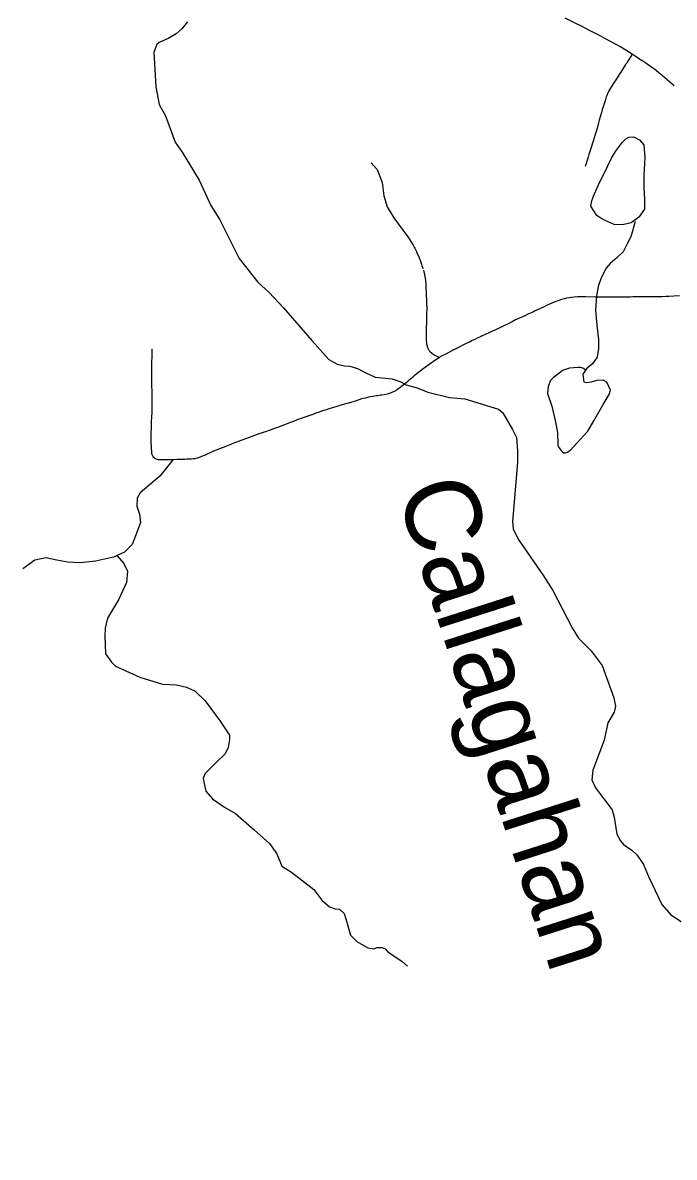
# Model space of a CAD drawing. Extents: x -19 to 366, y -4 to 359.
# Drawn here: x 143.365 to 144.057, y 187.329 to 188.535 of the extents above; entities that cross this region are included whole.
import ezdxf

# ---------------------------------------------------------------- set-up
doc = ezdxf.new("R2010")
doc.units = 0
for name, color, linetype in [('R_ROW', 7, 'Continuous'), ('R_ROW Annot', 7, 'Continuous'), ('R_Temp Easement', 7, 'Continuous'), ('Sheet Fence', 7, 'Continuous'), ('T_Indications', 7, 'Continuous')]:
    doc.layers.add(name, color=color, linetype=linetype)

msp = doc.modelspace()

# ---------------------------------------------------------------- linework, layer by layer
at = {"layer": 'R_ROW'}
for points in [[(144.0128, 188.5014), (144.0042, 188.5069), (143.9996, 188.5096), (143.9959, 188.5118), (143.9906, 188.5146), (143.9838, 188.5183), (143.9788, 188.5209), (143.9708, 188.5251), (143.9681, 188.5265), (143.9576, 188.5319), (143.9551, 188.5332), (143.9417, 188.54)], [(144.0128, 188.5014), (144.0075, 188.4931), (144.0069, 188.4921), (144.0062, 188.4912), (144.0057, 188.4904), (144.0036, 188.4871), (144.0006, 188.4823), (143.9997, 188.481), (143.9977, 188.478), (143.9967, 188.4764), (143.9931, 188.471), (143.9926, 188.4701), (143.9908, 188.4672), (143.9897, 188.4655), (143.9877, 188.4619), (143.987, 188.4606), (143.9858, 188.4576), (143.9854, 188.4567), (143.9852, 188.4561), (143.9839, 188.452), (143.9829, 188.4487), (143.9822, 188.4466), (143.9809, 188.4427), (143.98, 188.4397), (143.9786, 188.4348), (143.9778, 188.4314), (143.977, 188.4286), (143.9762, 188.4253), (143.9749, 188.4205), (143.9735, 188.4161), (143.9714, 188.4091), (143.9707, 188.4071), (143.9691, 188.4025), (143.9681, 188.3993), (143.9667, 188.3949), (143.9659, 188.3922), (143.9627, 188.3822)], [(144.0575, 188.4679), (144.045, 188.4785), (144.0431, 188.48), (144.0363, 188.4855), (144.0346, 188.4868), (144.0288, 188.4909), (144.0273, 188.492), (144.0231, 188.4948), (144.0217, 188.4957), (144.0207, 188.4964), (144.0192, 188.4974), (144.0128, 188.5014)], [(143.7909, 188.2721), (143.7914, 188.2702), (143.7916, 188.2691), (143.792, 188.2671), (143.7928, 188.2633), (143.7929, 188.2626), (143.7931, 188.2612), (143.7933, 188.2597), (143.7934, 188.2587), (143.7934, 188.2578), (143.7937, 188.2544), (143.7937, 188.2537), (143.794, 188.247), (143.794, 188.246), (143.7943, 188.2393), (143.7943, 188.2381), (143.7944, 188.2345), (143.7945, 188.234), (143.7945, 188.2314), (143.7945, 188.2304), (143.7944, 188.2256), (143.7943, 188.2226), (143.7941, 188.214), (143.794, 188.2123), (143.794, 188.2088), (143.794, 188.2041), (143.794, 188.1998), (143.794, 188.1976), (143.794, 188.1967), (143.7941, 188.1953), (143.7943, 188.1944), (143.7944, 188.1936), (143.7947, 188.1924), (143.7949, 188.1915), (143.795, 188.1909), (143.7954, 188.1898), (143.7956, 188.1894), (143.7962, 188.1881), (143.7965, 188.1876), (143.7968, 188.1871), (143.7976, 188.1859), (143.7986, 188.1848), (143.7991, 188.1843), (143.7999, 188.1834), (143.8007, 188.1829), (143.8014, 188.1825), (143.8019, 188.1822), (143.8028, 188.1817), (143.8038, 188.1812), (143.8079, 188.1792)], [(144.0632, 188.2447), (144.057, 188.2443), (144.0517, 188.2441), (144.0484, 188.244), (144.0446, 188.2437), (144.0422, 188.2436), (144.032, 188.2436), (144.0277, 188.2436), (144.0133, 188.2435), (144.0109, 188.2434), (144.0025, 188.2433), (143.9996, 188.2433), (143.9963, 188.2433), (143.9871, 188.2433), (143.9785, 188.2434), (143.9736, 188.2434), (143.9635, 188.2435), (143.9612, 188.2436), (143.9578, 188.2435), (143.9545, 188.2435), (143.951, 188.2433), (143.9482, 188.243), (143.9462, 188.2427), (143.9429, 188.2421), (143.9407, 188.2416), (143.9377, 188.2407), (143.934, 188.2395), (143.9315, 188.2386), (143.9274, 188.2369), (143.925, 188.2358), (143.9219, 188.2343), (143.9192, 188.233), (143.909, 188.2282), (143.9073, 188.2274), (143.902, 188.225), (143.8995, 188.2238), (143.8954, 188.222), (143.8889, 188.219), (143.8852, 188.2171), (143.8823, 188.2157), (143.8764, 188.2128), (143.8714, 188.2104), (143.8645, 188.2072), (143.8566, 188.2036), (143.8535, 188.2022), (143.8515, 188.2012), (143.8481, 188.1995), (143.8456, 188.1983), (143.8429, 188.197), (143.8398, 188.1955), (143.8371, 188.1942), (143.8261, 188.1888), (143.8232, 188.1873), (143.8223, 188.1868), (143.8212, 188.1862), (143.8166, 188.1838), (143.8161, 188.1835), (143.8154, 188.1831), (143.8141, 188.1824), (143.8122, 188.1816), (143.8097, 188.1804), (143.8093, 188.1802), (143.8084, 188.1795), (143.8079, 188.1792)], [(143.5025, 188.1883), (143.5023, 188.1813), (143.5022, 188.1728), (143.5021, 188.1698), (143.5022, 188.1628), (143.5022, 188.1603), (143.5022, 188.1567), (143.5022, 188.1542), (143.5022, 188.1517), (143.5022, 188.1485), (143.5024, 188.1435), (143.5025, 188.1392), (143.5025, 188.1362), (143.5025, 188.1326), (143.5023, 188.1281), (143.5023, 188.1258), (143.5023, 188.1211), (143.5023, 188.1199), (143.5021, 188.1166), (143.502, 188.1143), (143.5019, 188.1123), (143.5018, 188.1068), (143.5017, 188.1038), (143.5015, 188.0983), (143.5015, 188.0975), (143.5014, 188.0925), (143.5014, 188.089), (143.5015, 188.0874), (143.5017, 188.0855), (143.5019, 188.0825), (143.5019, 188.0815), (143.502, 188.0798), (143.502, 188.0786), (143.5022, 188.0774), (143.5024, 188.0765), (143.5026, 188.0759), (143.5033, 188.0747), (143.5035, 188.0744), (143.5037, 188.074), (143.5045, 188.0731), (143.5049, 188.0727), (143.5058, 188.072), (143.5063, 188.0718), (143.5067, 188.0715), (143.5076, 188.0711), (143.5082, 188.0709), (143.5091, 188.0708), (143.5136, 188.0707), (143.5171, 188.0706), (143.5179, 188.0706), (143.5223, 188.0707), (143.5238, 188.0707), (143.5293, 188.0709), (143.5327, 188.071), (143.5375, 188.0711), (143.5395, 188.0712), (143.5432, 188.0713), (143.5445, 188.0714), (143.5469, 188.0716), (143.5477, 188.0717), (143.5484, 188.0718), (143.5489, 188.0719)], [(143.8079, 188.1792), (143.8055, 188.1774), (143.8039, 188.1764), (143.8021, 188.1751), (143.8003, 188.1739), (143.7984, 188.1726), (143.7971, 188.1717), (143.7894, 188.166), (143.787, 188.1642), (143.7812, 188.1595), (143.7797, 188.1582), (143.7772, 188.1562), (143.776, 188.1552), (143.774, 188.1535), (143.7726, 188.1523), (143.7708, 188.1509), (143.7677, 188.1484), (143.7658, 188.1469), (143.7647, 188.146), (143.7635, 188.1452), (143.7621, 188.1442), (143.7615, 188.1438), (143.76, 188.143), (143.7575, 188.1418), (143.7566, 188.1415), (143.7524, 188.1401), (143.7494, 188.1395), (143.7467, 188.1391), (143.7455, 188.1389), (143.7427, 188.1384), (143.7412, 188.1382), (143.7371, 188.1375), (143.7352, 188.1372), (143.7328, 188.1368), (143.7314, 188.1365), (143.729, 188.136), (143.727, 188.1355), (143.7252, 188.135), (143.7207, 188.1335), (143.7195, 188.1332), (143.7149, 188.1317), (143.7113, 188.1307), (143.7097, 188.1303), (143.7048, 188.1288), (143.7011, 188.1277), (143.6999, 188.1273), (143.6945, 188.1257), (143.6904, 188.1244), (143.6869, 188.1232), (143.6849, 188.1226), (143.6793, 188.1207), (143.6778, 188.1201), (143.675, 188.1191), (143.6735, 188.1186), (143.6704, 188.1175), (143.6682, 188.1167), (143.6628, 188.1149), (143.6613, 188.1144), (143.6589, 188.1136), (143.6576, 188.1131), (143.6554, 188.1123), (143.6469, 188.1089), (143.6451, 188.1082), (143.6434, 188.1075), (143.6422, 188.107), (143.6362, 188.1048), (143.6345, 188.1042), (143.628, 188.1019), (143.6262, 188.1013), (143.6242, 188.1006), (143.6163, 188.0978), (143.6143, 188.0971), (143.6116, 188.0961), (143.6041, 188.0932), (143.6021, 188.0925), (143.5896, 188.0879), (143.5885, 188.0875), (143.5865, 188.0867), (143.5824, 188.0851), (143.5794, 188.0839), (143.5762, 188.0826), (143.5735, 188.0816), (143.568, 188.0794), (143.5671, 188.079), (143.5605, 188.0761), (143.559, 188.0754), (143.5551, 188.0737), (143.5538, 188.0732), (143.5516, 188.0724), (143.5506, 188.0722), (143.5489, 188.0719)]]:
    msp.add_lwpolyline(points, dxfattribs=at)
at = {"layer": 'R_ROW Annot'}
for points in [[(143.7354, 188.3861), (143.7418, 188.3791), (143.7471, 188.365), (143.7489, 188.3509), (143.7524, 188.3391), (143.7595, 188.3274), (143.7745, 188.3074), (143.7764, 188.3043), (143.7794, 188.2995), (143.78, 188.2984), (143.7812, 188.2963), (143.7819, 188.2952), (143.7828, 188.2932), (143.7835, 188.2917), (143.7845, 188.2897), (143.7856, 188.2871), (143.7864, 188.2852), (143.7871, 188.2835), (143.7889, 188.2783), (143.7894, 188.2767), (143.7901, 188.2747), (143.7905, 188.2733)], [(143.525, 188.0708), (143.511, 188.0528), (143.4899, 188.0353), (143.487, 188.0294), (143.4864, 188.0212), (143.4893, 188.0124), (143.4905, 188.0036), (143.487, 187.9943), (143.4817, 187.9802), (143.4735, 187.972), (143.4618, 187.9668), (143.4425, 187.9627), (143.4267, 187.9609), (143.4133, 187.9615), (143.4016, 187.9638), (143.3899, 187.9662), (143.3782, 187.9638), (143.3653, 187.9545)]]:
    msp.add_lwpolyline(points, dxfattribs=at)
at = {"layer": 'R_Temp Easement'}
for points in [[(143.5403, 188.5359), (143.5344, 188.5286), (143.5282, 188.5233), (143.5206, 188.5185), (143.5104, 188.5141), (143.5079, 188.512), (143.5045, 188.5036), (143.5068, 188.467), (143.5101, 188.448), (143.517, 188.4361), (143.5273, 188.408), (143.5348, 188.3972), (143.5527, 188.3675), (143.565, 188.3406), (143.5742, 188.3262), (143.5954, 188.2843), (143.6151, 188.2592), (143.6272, 188.2482), (143.6423, 188.2318), (143.6726, 188.1973), (143.6905, 188.1771), (143.6993, 188.172), (143.7073, 188.1701), (143.7128, 188.17), (143.7209, 188.1675), (143.7297, 188.1628), (143.7398, 188.1581), (143.7578, 188.1563), (143.7671, 188.1531), (143.7728, 188.1501), (143.7844, 188.1469), (143.7958, 188.1422), (143.8186, 188.1366), (143.8349, 188.1352), (143.8706, 188.1241)], [(144.0263, 188.3917), (144.025, 188.3725), (144.0253, 188.3589), (144.026, 188.3478), (144.026, 188.3368), (144.0197, 188.3282), (144.0118, 188.3222), (144.0026, 188.3203), (143.9937, 188.3206), (143.9839, 188.3247), (143.9795, 188.3273), (143.9751, 188.3301), (143.969, 188.3399), (143.97, 188.3456), (143.9716, 188.3506), (143.9766, 188.362), (143.9864, 188.3822), (143.9908, 188.3911), (143.9949, 188.398), (144.0025, 188.4081), (144.006, 188.4116), (144.0091, 188.4132), (144.0142, 188.4135), (144.0205, 188.4104), (144.0253, 188.4053), (144.0263, 188.3917)], [(144.0159, 188.3235), (144.0115, 188.3074), (144.0074, 188.3001), (144.0033, 188.2913), (143.9969, 188.2853), (143.9894, 188.279), (143.9852, 188.2739), (143.9799, 188.2638), (143.9767, 188.2546), (143.9748, 188.2448), (143.9739, 188.2294), (143.9752, 188.2136), (143.9768, 188.1984), (143.9768, 188.1886), (143.9755, 188.1795), (143.9705, 188.1722), (143.9648, 188.1678)], [(143.9634, 188.1655), (143.9603, 188.1676), (143.9583, 188.1684), (143.9556, 188.1684), (143.9509, 188.1682), (143.946, 188.1676), (143.9388, 188.1652), (143.9347, 188.1621), (143.929, 188.1579), (143.9259, 188.1545), (143.9234, 188.1482), (143.9227, 188.1409), (143.9275, 188.1273), (143.931, 188.1122), (143.9335, 188.0995), (143.9339, 188.0856), (143.9349, 188.0833), (143.9374, 188.0804), (143.9388, 188.0787), (143.9402, 188.0778), (143.9424, 188.0777), (143.9439, 188.0784), (143.9456, 188.0794), (143.9468, 188.0803), (143.9538, 188.0882), (143.9655, 188.1008), (143.9721, 188.1119), (143.9819, 188.1293), (143.9882, 188.1397), (143.9898, 188.1444), (143.986, 188.1529), (143.9819, 188.1551), (143.9752, 188.1548), (143.9692, 188.1529), (143.9642, 188.1523), (143.9616, 188.1529), (143.9607, 188.1614), (143.9648, 188.1678)], [(143.8706, 188.1241), (143.8754, 188.1202), (143.8857, 188.1027), (143.8897, 188.0942), (143.8911, 188.0798), (143.891, 188.0676), (143.8856, 188.0046), (143.8864, 187.997), (143.8915, 187.9858), (143.9179, 187.9481), (143.9284, 187.9315), (143.949, 187.8917), (143.9559, 187.8809), (143.9691, 187.8673), (143.9807, 187.8518), (143.9932, 187.8173), (143.9951, 187.8086), (143.9936, 187.8019), (143.987, 187.7909), (143.9829, 187.7724), (143.9711, 187.7403), (143.97, 187.73), (143.9737, 187.7215), (143.9916, 187.6984), (143.9937, 187.6906), (143.9966, 187.6724), (144.0003, 187.6652), (144.0035, 187.6614), (144.0125, 187.6554), (144.0182, 187.6499), (144.0247, 187.6403), (144.03, 187.6272), (144.0444, 187.5975), (144.0539, 187.5865), (144.0648, 187.5795)]]:
    msp.add_lwpolyline(points, dxfattribs=at)
at = {"layer": 'Sheet Fence'}
for points in [[(146.7783, 1.697), (146.5788, 10.3131), (146.3785, 18.9294), (146.1776, 27.5458), (145.9759, 36.1624), (145.7736, 44.7791), (145.5705, 53.396), (145.3668, 62.013), (145.1624, 70.6301), (144.9572, 79.2474), (144.7514, 87.8648), (144.5449, 96.4823), (144.3377, 105.1), (144.1299, 113.7179), (143.9213, 122.3359), (143.712, 130.954), (143.5021, 139.5723), (143.2915, 148.1907), (143.0802, 156.8092), (142.8682, 165.4279), (142.6555, 174.0468), (142.4422, 182.6658), (142.2282, 191.2849), (142.0135, 199.9042), (141.7981, 208.5236), (141.582, 217.1432), (141.3653, 225.7629), (141.1479, 234.3828), (140.9298, 243.0028), (140.711, 251.623), (140.4916, 260.2433), (140.2715, 268.8638), (140.0508, 277.4844), (139.8293, 286.1051), (139.6072, 294.726), (139.3845, 303.3471), (139.161, 311.9683), (138.937, 320.5896), (138.7122, 329.2111), (138.4868, 337.8328), (138.2607, 346.4546)], [(0, 180.8999), (7.1228, 180.9044), (14.2457, 180.9176), (21.3685, 180.9397), (28.4912, 180.9706), (35.614, 181.0103), (42.7366, 181.0589), (49.8592, 181.1163), (56.9818, 181.1825), (64.1042, 181.2575), (71.2266, 181.3414), (78.3488, 181.4341), (85.4709, 181.5357), (92.5929, 181.646), (99.7147, 181.7652), (106.8364, 181.8933), (113.9579, 182.0301), (121.0793, 182.1758), (128.2005, 182.3303), (135.3214, 182.4936), (142.4422, 182.6658), (149.5627, 182.8468), (156.683, 183.0366), (163.8031, 183.2352), (170.9229, 183.4427), (178.0425, 183.659), (185.1617, 183.8841), (192.2807, 184.1181), (199.3994, 184.3608), (206.5178, 184.6124), (213.6359, 184.8728), (220.7537, 185.1421), (227.8711, 185.4201), (234.9881, 185.707), (242.1048, 186.0027), (249.2212, 186.3073), (256.3371, 186.6206), (263.4526, 186.9428), (270.5678, 187.2738), (277.6825, 187.6136), (284.7968, 187.9622), (291.9107, 188.3197), (299.0241, 188.6859), (306.1371, 189.061), (313.2495, 189.4449), (320.3615, 189.8377), (327.4731, 190.2392), (334.5841, 190.6495), (341.6946, 191.0687)]]:
    msp.add_spline(points, degree=3, dxfattribs=at)
at = {"layer": 'T_Indications'}
msp.add_lwpolyline([(143.4655, 187.9684), (143.4727, 187.96), (143.4765, 187.9518), (143.4756, 187.9398), (143.4669, 187.9214), (143.4553, 187.9021), (143.4529, 187.8914), (143.4524, 187.8828), (143.4533, 187.8639), (143.4596, 187.8552), (143.464, 187.8509), (143.4896, 187.8393), (143.5137, 187.832), (143.5287, 187.8311), (143.5393, 187.8287), (143.5485, 187.8243), (143.5591, 187.8142), (143.575, 187.7924), (143.5851, 187.7775), (143.5851, 187.7731), (143.5837, 187.7644), (143.5803, 187.7576), (143.5702, 187.748), (143.5591, 187.7369), (143.5571, 187.732), (143.5581, 187.7263), (143.56, 187.718), (143.5668, 187.7098), (143.5798, 187.7011), (143.5914, 187.6944), (143.6112, 187.677), (143.6276, 187.6625), (143.6353, 187.6514), (143.6407, 187.6383), (143.6508, 187.6321), (143.6619, 187.6234), (143.6745, 187.6137), (143.6831, 187.6021), (143.6913, 187.5953), (143.6971, 187.5929), (143.702, 187.5925), (143.7068, 187.5881), (143.7087, 187.5823), (143.7136, 187.5649), (143.7203, 187.5582), (143.7319, 187.5514), (143.7387, 187.5504), (143.7416, 187.5519), (143.7473, 187.5519), (143.7502, 187.5504), (143.7527, 187.5475), (143.7599, 187.5427), (143.7681, 187.5374), (143.7739, 187.5321)], dxfattribs=at)

# ---------------------------------------------------------------- texts
at = {"layer": 'R_Temp Easement'}
msp.add_text('Callagahan', height=0.08, rotation=287.802, dxfattribs=at).set_placement((143.7618, 188.0377))

doc.saveas('drawing.dxf')
